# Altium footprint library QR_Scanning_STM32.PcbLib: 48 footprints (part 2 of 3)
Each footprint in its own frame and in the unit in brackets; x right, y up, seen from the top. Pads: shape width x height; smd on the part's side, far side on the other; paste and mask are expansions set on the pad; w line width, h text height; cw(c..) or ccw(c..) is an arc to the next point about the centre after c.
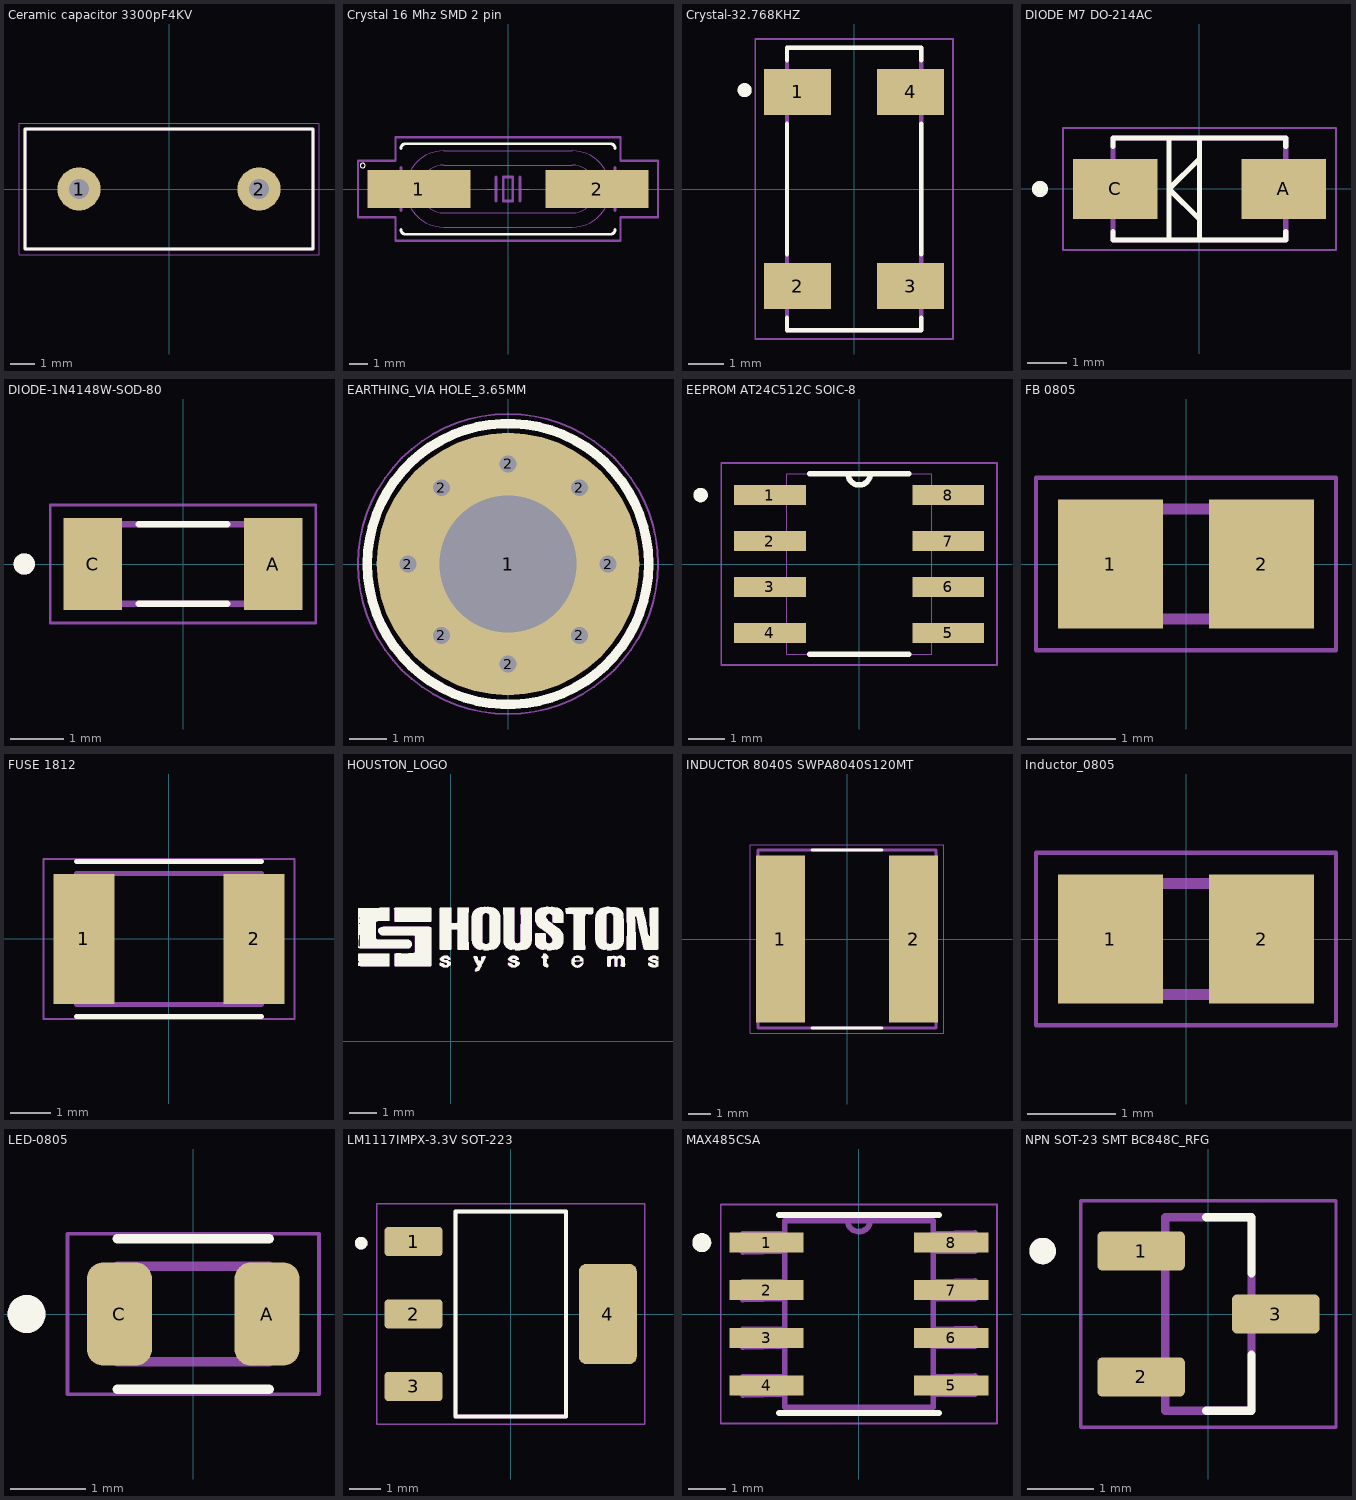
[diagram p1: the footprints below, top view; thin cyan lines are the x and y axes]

## Ceramic capacitor 3300pF4KV [mm] "Ceramic capacitor 3300pF4KV, Tension nominale 400Vac(r.m.s.), 4KV ESD, DE2E3SA332MA3BY02F"
pads (2):
  round 1.8 hole 0.85: 1(-3.75,0) 2(3.75,0)
Top Overlay:
  lines w0.127: -6,-2.5 -6,2.5 6,2.5 6,-2.5 -6,-2.5
Mechanical 13:
  lines w0.127: -6,-2.5 -6,2.5 6,2.5 6,-2.5 -6,-2.5
Mechanical 15:
  lines w0.05: -6.25,-2.75 -6.25,2.75 6.25,2.75 6.25,-2.75 -6.25,-2.75
3D body "step_temp.STEP": height 15, standoff -25, extent -6,-2.5 6,2.5

## Crystal 16 Mhz SMD 2 pin [mm] "16 MHz Â±30ppm Crystal 20pF 60 Ohms HC-49/US FOXSDLF/128-20 16 Mhz Crystal SMD –CSM-4ALX(28ALX) SMT12.5mmX4.85mmX4mm"
pads (2):
  rect 5.5x2 smd: 1(-4.75,0) 2(4.75,0)
Top Overlay:
  circle w0: c-7.75,1.25 r0.127
  lines w0.152: -5.715,-2.159 ccw(c-5.461,-2.159) -5.461,-2.413 5.461,-2.413 ccw(c5.461,-2.159) 5.715,-2.159 ; -5.715,2.159 cw(c-5.461,2.159) -5.461,2.413 5.461,2.413 cw(c5.461,2.159) 5.715,2.159
Mechanical 13:
  lines w0.051: -1.143,0 -0.635,0 ; 0.635,0 1.143,0 ; -5.114,-1.136 cw(c-3.429,0) -5.114,1.136 cw(c-3.429,0) -3.429,2.032 3.429,2.032 cw(c3.429,0) 5.114,1.136 cw(c3.429,0) 5.114,-1.136 cw(c3.429,0) 3.429,-2.032 -3.429,-2.032 cw(c-3.429,0) -5.114,-1.136 ; -3.986,-1.141 cw(c-3.429,0) -3.986,1.141 cw(c-3.429,0) -3.429,1.27 3.429,1.27 cw(c3.429,0) 3.986,1.141 cw(c3.429,0) 3.986,-1.141 cw(c3.429,0) 3.429,-1.27 -3.429,-1.27 cw(c-3.429,0) -3.986,-1.141
  lines w0.152: -5.715,-1.143 -5.715,1.143 ; -5.715,-0.381 -6.477,-0.381 -6.477,0.381 -5.715,0.381 ; -0.635,-0.635 -0.635,0 -0.635,0.635 ; 0.635,-0.635 0.635,0 0.635,0.635 ; 5.715,-1.143 5.715,-0.381 ; 5.715,1.143 5.715,0.381 ; 5.715,-0.381 6.477,-0.381 6.477,0.381 5.715,0.381 ; 5.715,-0.381 5.715,0.381 ; -0.254,-0.635 0.254,-0.635 0.254,0.635 -0.254,0.635 -0.254,-0.635
Mechanical 15:
  lines w0.127: -8,-1.5 -6,-1.5 -6,-2.75 6,-2.75 6,-1.5 8,-1.5 8,1.5 6,1.5 6,2.75 -6,2.75 -6,1.5 -8,1.5 -8,-1.5
3D body "step_temp.STEP": height 4.5, standoff 0, extent -6.75,-2.5 6.75,2.5

## Crystal-32.768KHZ [mm] "32.768 kHz Â±20ppm Crystal 6pF 50 kOhms 4-SOJ, 5.50mm pitch ABS25-32.768KHZ-6-T"
pads (4):
  rect 1.9x1.3 smd: 1(-1.6,2.75) 2(-1.6,-2.75) 3(1.6,-2.75) 4(1.6,2.75)
Top Overlay:
  circle w0.2: c-3.1,2.8 r0.1
  lines w0.127: -1.9,-3.65 -1.9,-4 1.9,-4 1.9,-3.65 ; -1.9,-1.85 -1.9,1.85 ; -1.9,3.65 -1.9,4 1.9,4 1.9,3.65 ; 1.9,-1.85 1.9,1.85
Mechanical 13:
  circle w0.2: c-3.1,2.8 r0.1
  lines w0.127: -1.9,-4 1.9,-4 1.9,4 -1.9,4 -1.9,-4
Mechanical 15:
  lines w0.05: -2.8,-4.25 2.8,-4.25 2.8,4.25 -2.8,4.25 -2.8,-4.25
3D body "step_temp.STEP": height 2.72, standoff 0.06, extent -2,-4 2,4

## DIODE M7 DO-214AC [mm] "M7 General Purpose SMD Rectifier Diode SMA (DO-214AC) 1A 1000V 1n4007  DIOM4325X250N"
height 2.5
pads (2):
  rect 2.12x1.5 smd: A(2.115,0) C(-2.115,0)
Top Overlay:
  circle w0.2: c-4,0 r0.1
  lines w0.127: -2.165,-1.07 -2.165,-1.28 2.165,-1.28 2.165,-1.07 ; -2.165,1.07 -2.165,1.28 2.165,1.28 2.165,1.07 ; -0.762,-1.27 -0.762,1.27 ; 0,-1.28 0,-0.762 ; 0,1.28 0,0.762 ; 0,-0.762 0,0.762 ; 0,-0.762 -0.762,0 0,0.762
Mechanical 13:
  circle w0.2: c-4,0 r0.1
  lines w0.127: -2.165,-1.28 2.165,-1.28 2.165,1.28 -2.165,1.28 -2.165,-1.28
Mechanical 15:
  lines w0.05: -3.425,-1.53 3.425,-1.53 3.425,1.53 -3.425,1.53 -3.425,-1.53
3D body "step_temp.STEP": height 2.5, standoff 0, extent -2.57,-1.28 2.57,1.28

## DIODE-1N4148W-SOD-80 [mm] "DIODE-1N4148W-SOD-80 is a general-purpose silicon diode LL4148_L1G"
pads (2):
  rect 1.11x1.73 smd: A(1.705,0) C(-1.705,0)
Top Overlay:
  circle w0.2: c-3,0 r0.1
  lines w0.127: -0.83,-0.75 0.83,-0.75 ; -0.83,0.75 0.83,0.75
Mechanical 13:
  circle w0.2: c-3,0 r0.1
  lines w0.127: -1.75,-0.75 1.75,-0.75 1.75,0.75 -1.75,0.75 -1.75,-0.75
Mechanical 15:
  lines w0.05: -2.51,-1.115 2.51,-1.115 2.51,1.115 -2.51,1.115 -2.51,-1.115
3D body "LL4148 L1G.STEP": height 1.57, standoff -0.03, extent -1.75,-0.762 1.75,0.826

## EARTHING_VIA HOLE_3.65MM [mm] "EARTHING VIA HOLE 3.65MM"
pads (9):
  round 7 hole 3.65: 1(0,0)
  round 0.5 hole 0.45: 2(-2.667,0) 2(-1.778,-1.905) 2(-1.778,2.032) 2(0,-2.667) 2(0,2.667) 2(1.905,-1.905) 2(1.905,2.032) 2(2.667,0)
Top Overlay:
  circle w0.254: c0,0 r3.75
Mechanical 15:
  circle w0.05: c0,0 r4

## EEPROM AT24C512C SOIC-8 [mil] "EEPROM Memory IC 512Kb (64K x 8) IÂ²C 400 kHz 900 ns SOIC-8 AT24C512C-SSHM-T"
pads (8):
  rect 78x22 smd: 1(-97,75) 2(-97,25) 3(-97,-25) 4(-97,-75) 5(97,-75) 6(97,-25) 7(97,25) 8(97,75)
Top Overlay:
  circle w7.87: c-172.48,75 r3.94
  lines w6: -54,-98 54,-98 ; -54,98 -12,98 ; 54,98 12,98 ; -12,98 ccw(c0,98) 12,98 ; -12,98 12,98
Mechanical 13:
  lines w0: -12,98 ccw(c0,98) 12,98 ; -12,98 12,98 ; -12,98 -79,98 -79,-98 79,-98 79,98 12,98 ; -122,-85 -122,-65 -79,-65 -79,-85 -122,-85 ; -122,-35 -122,-15 -79,-15 -79,-35 -122,-35 ; -122,15 -122,35 -79,35 -79,15 -122,15 ; -122,65 -122,85 -79,85 -79,65 -122,65 ; 79,-85 79,-65 122,-65 122,-85 79,-85 ; 79,-35 79,-15 122,-15 122,-35 79,-35 ; 79,15 79,35 122,35 122,15 79,15 ; 79,65 79,85 122,85 122,65 79,65
Mechanical 15:
  lines w1.97: -150,-110 -150,110 150,110 150,-110 -150,-110
3D body "step_temp.STEP": height 68.9, standoff 0, extent -118.11,-96.46 118.11,96.46

## FB 0805 [mm] "MH2029-101Y-Bourns Inc.-Ferrite Bead, 100 Ohms @ 100 MHz , Signal Line Ferrite Bead 0805 (2012 Metric) 2A 100mOhm"
pads (2):
  rect 1.2x1.47 smd: 1(-0.86,0) 2(0.86,0)
Mechanical 13:
  lines w0.127: -1,-0.625 -1,0.625 1,0.625 1,-0.625 -1,-0.625
Mechanical 15:
  lines w0.05: -1.708,-0.983 -1.708,0.983 1.708,0.983 1.708,-0.983 -1.708,-0.983

## FUSE 1812 [mm] "Polymeric PTC Resettable Fuse 60V 100 mA Ih Surface Mount 1812 (4532 Metric), Concave, MF-MSMF010-2"
pads (2):
  rect 1.5x3.2 smd: 1(-2.1,0) 2(2.1,0)
Top Overlay:
  lines w0.127: -2.275,-1.913 2.275,-1.913 ; -2.275,1.913 2.275,1.913
Mechanical 13:
  lines w0.127: -2.275,-1.62 -2.275,1.62 2.275,1.62 2.275,-1.62 -2.275,-1.62
Mechanical 15:
  lines w0.05: -3.1,-1.977 3.1,-1.977 3.1,1.977 -3.1,1.977 -3.1,-1.977
3D body "step_temp.STEP": height 0.85, standoff 0, extent -2.275,-1.62 2.275,1.62

## HOUSTON_LOGO [mm]
Top Overlay:
  drawing of 26 lines, arcs and shapes, not listed
Mechanical 13:
  drawing of 26 lines, arcs and shapes, not listed

## INDUCTOR 8040S SWPA8040S120MT [mm]
height 4.2
pads (2):
  rect 2.2x7.5 smd: 1(-3,0) 2(3,0)
Top Overlay:
  lines w0.127: -1.58,-4 1.58,-4 ; -1.58,4 1.58,4
Mechanical 13:
  lines w0.127: -4,-4 4,-4 4,4 -4,4 -4,-4
Mechanical 15:
  lines w0.05: -4.35,-4.25 4.35,-4.25 4.35,4.25 -4.35,4.25 -4.35,-4.25
3D body "step_temp.STEP": height 4, standoff 0, extent -4,-4 4,4

## Inductor_0805 [mm] "Inductor_0805 MLZ2012M1R5HT000"
pads (2):
  rect 1.2x1.47 smd: 1(-0.86,0) 2(0.86,0)
Mechanical 13:
  lines w0.127: -1,-0.63 1,-0.63 1,0.63 -1,0.63 -1,-0.63
Mechanical 15:
  lines w0.05: -1.708,-0.983 1.708,-0.983 1.708,0.983 -1.708,0.983 -1.708,-0.983

## LED-0805 [mm] "Red 640nm LED Indication - Discrete 1.85V 0805 (2012 Metric) SMT APT2012SRCPRV"
pads (2):
  rrect50% 0.86x1.36 smd: A(0.975,0) C(-0.975,0)
Top Overlay:
  circle w0.3: c-2.2,0 r0.1
  lines w0.127: -1,-0.995 1,-0.995 ; -1,0.995 1,0.995
Mechanical 13:
  circle w0.3: c-2.2,0 r0.1
  lines w0.127: -1,-0.63 1,-0.63 1,0.63 -1,0.63 -1,-0.63
Mechanical 15:
  lines w0.05: -1.66,-1.059 1.66,-1.059 1.66,1.059 -1.66,1.059 -1.66,-1.059
3D body "step_temp.STEP": height 0.75, standoff 0, extent -1,-0.625 1,0.625

## LM1117IMPX-3.3V SOT-223 [mm] "LM1117IMPX-3.3V 800-mA 15-V linear voltage regulator SOT230P700X180-4N"
height 1.8
pads (4):
  rrect25% 1.84x0.93 smd: 1(-3.085,2.3) 2(-3.085,0) 3(-3.085,-2.3)
  rrect25% 1.84x3.19 smd: 4(3.085,0)
Top Overlay:
  circle w0.2: c-4.75,2.25 r0.1
  lines w0.127: -1.75,-3.25 1.75,-3.25 1.75,3.25 -1.75,3.25 -1.75,-3.25
Mechanical 13:
  circle w0.2: c-4.75,2.25 r0.1
  lines w0.127: -1.75,-3.25 1.75,-3.25 1.75,3.25 -1.75,3.25 -1.75,-3.25
Mechanical 15:
  lines w0.05: -4.255,-3.5 -4.255,3.5 4.255,3.5 4.255,-3.5 -4.255,-3.5
3D body "step_temp.STEP": height 1.8, standoff 0, extent -3.499,-3.25 3.499,3.25

## MAX485CSA [mil] "MAX485CSA-RS-485/RS-422 Transceivers, SOIC-8"
pads (8):
  rect 78x21 smd: 1(-97,75) 2(-97,25) 3(-97,-25) 4(-97,-75) 5(97,-75) 6(97,-25) 7(97,25) 8(97,75)
Top Overlay:
  circle w10: c-165,75 r5
  lines w6: -84,-104 84,-104 ; -84,104 84,104
Mechanical 13:
  lines w6: -12,98.08 ccw(c0,98.5) 12,98.92 ; -122,-85 -78,-84 -78,-66 -122,-66 -122,-85 ; -122,-35 -78,-34 -78,-16 -122,-16 -122,-35 ; -122,15 -78,16 -78,34 -122,34 -122,15 ; -122,65 -78,66 -78,84 -122,84 -122,65 ; -78,-98 -78,98 -12,98 78,98 78,-98 -78,-98 ; 78,-84 122,-84 122,-65 78,-66 78,-84 ; 78,-34 122,-34 122,-15 78,-16 78,-34 ; 78,16 122,16 122,35 78,34 78,16 ; 78,66 122,66 122,85 78,84 78,66
Mechanical 15:
  lines w1.97: -145,-115 145,-115 145,115 -145,115 -145,-115
3D body "step_temp.STEP": height 68.9, standoff 0, extent -118.11,-96.46 118.11,96.46

## NPN SOT-23 SMT BC848C_RFG [mm] "NPN SOT-23 SMT BC848C_RFG SOT95P237X112-3N"
height 1.12
pads (3):
  rrect25% 1.32x0.59 smd: 1(-1.015,0.95) 2(-1.015,-0.95) 3(1.015,0)
Top Overlay:
  circle w0.2: c-2.5,0.95 r0.1
  lines w0.127: -0.035,-1.46 0.65,-1.46 0.65,-0.615 ; -0.035,1.46 0.65,1.46 0.65,0.615
Mechanical 13:
  circle w0.2: c-2.5,0.95 r0.1
  lines w0.127: -0.65,-1.46 0.65,-1.46 0.65,1.46 -0.65,1.46 -0.65,-1.46
Mechanical 15:
  lines w0.05: -1.925,-1.71 1.925,-1.71 1.925,1.71 -1.925,1.71 -1.925,-1.71
3D body "step_temp.STEP": height 1.12, standoff 0, extent -1.188,-1.46 1.188,1.46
